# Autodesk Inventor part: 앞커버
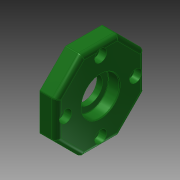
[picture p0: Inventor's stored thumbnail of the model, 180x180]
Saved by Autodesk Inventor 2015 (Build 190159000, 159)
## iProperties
Created: 2015-11
Part Number: 앞커버
Material: 알루미늄 6061
Document SubType Name: Modeling
Designer: mduedu
Density: 1 g/cm^3
Appearance: 매끄러움 - 짙은 산림 녹색
Author: mduedu
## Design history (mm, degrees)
sketch "스케치5" dims "d66" = 58
  geometry: L1 (12.012, 29)-(29, 12.012); L2 (29, 12.012)-(29, -12.012); L3 (29, -12.012)-(12.012, -29); L4 (12.012, -29)-(-12.012, -29); L5 (-12.012, -29)-(-29, -12.012); L6 (-29, -12.012)-(-29, 12.012); L7 (-29, 12.012)-(-12.012, 29); L8 (-12.012, 29)-(12.012, 29); 4 further points
  constraints: 16 end point, 2 coincident, 2 vertical alignment, 1 midpoint, 19 other
extrude "돌출2" new body sketch "스케치5" distance "d67" = 11; taper "d68" = 0 deg
sketch "스케치6"
  geometry: C1 r 16 at (0, 0); 1 further point
  constraints: 1 centre point, 1 coincident
  dimensions: "d69" = 32 diameter of C1
extrude "돌출3" join sketch "스케치6" distance "d70" = 3; taper "d71" = 0 deg
hole "구멍7" diameter "d98" = 28; stored, may be unused: countersink angle "d102" = 90 deg, drill point angle "d104" = 0 deg; dims "d99" = 6, "d100" = 4, "d101" = 2, "d103" = 3, "d145" = 10, "d146" = 10
hole "구멍8" diameter "d107" = 25; stored, may be unused: countersink angle "d111" = 90 deg, drill point angle "d113" = 0 deg; dims "d108" = 6, "d109" = 4, "d110" = 2, "d112" = 7.3, "d143" = 10, "d144" = 10
hole "구멍9" diameter "d116" = 17; stored, may be unused: countersink angle "d120" = 90 deg, drill point angle "d122" = 0 deg; dims "d114" = 10, "d115" = 10, "d117" = 6, "d118" = 4, "d119" = 2, "d121" = 7.7
chamfer "모따기2" distance "d123" = 0.6; stored, may be unused: second distance "d124" = 2, angle "d125" = 30 deg
fillet "모깎기11" dims "d126" = 0.3
fillet "모깎기12" dims "d127" = 1
fillet "모깎기13" dims "d128" = 3
fillet "모깎기14" dims "d129" = 3
fillet "모깎기15" dims "d130" = 0.3
sketch "스케치8" dims "d131" = 46
  geometry: 3 further points
  constraints: 2 vertical alignment, 1 coincident, 2 other
hole "구멍10" sketch "스케치8" at (0, 23) diameter "d132" = 4.5; stored, may be unused: countersink angle "d136" = 90 deg, drill point angle "d138" = 0 deg; dims "d133" = 6, "d134" = 8, "d135" = 4.6, "d137" = 7.7
node "솔리드2"
pattern_circular "원형 패턴4" dims angle "d140" = 360 deg
